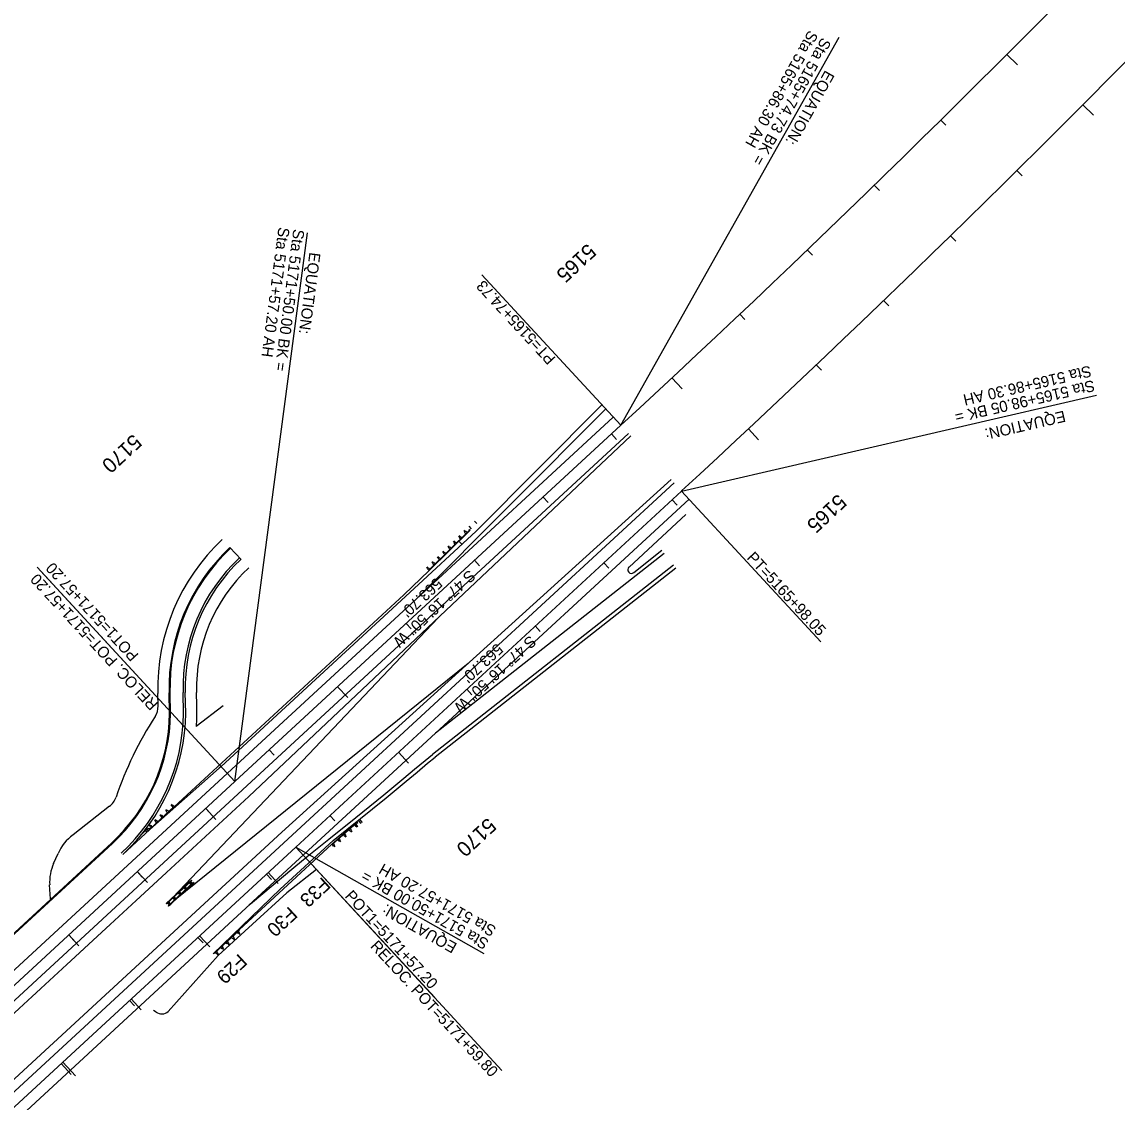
# Model space of a CAD drawing. Extents: x 2160877 to 2175861, y 601747 to 617724.
# Drawn here: x 2171979 to 2173154, y 613431 to 614591 of the extents above; entities that cross this region are included whole.
import ezdxf

# ---------------------------------------------------------------- set-up
doc = ezdxf.new("R2010")
doc.units = 0
for name, color, linetype in [('RD_HC_Cl', 7, 'Continuous'), ('RD_HC_CL_Rel', 7, 'Continuous'), ('RD_HC_Data', 7, 'Continuous'), ('RD_HC_Data_Rel', 7, 'Continuous'), ('RD_HC_Data_Tic', 7, 'Continuous'), ('RD_HC_Data_Tic_Rel', 7, 'Continuous'), ('RD_HC_TX_StaOther', 7, 'Continuous'), ('RD_PD_CstnLmt', 7, 'Continuous'), ('RD_PD_CstnLmt_TX', 7, 'Continuous'), ('RD_PD_Final_LnLine', 7, 'Continuous'), ('RD_PD_Final_TrvlWay', 7, 'Continuous'), ('RD_PD_GR', 7, 'Continuous'), ('RD_PD_MedBWall', 7, 'Continuous')]:
    doc.layers.add(name, color=color, linetype=linetype)

msp = doc.modelspace()

# ---------------------------------------------------------------- linework, layer by layer
at = {"layer": 'RD_HC_Cl'}
for p, q in [((2172621.5, 614157.6), (2172207.3, 613775.1)), ((2172686.6, 614087), (2172272.5, 613704.6)), ((2172207.3, 613775.1), (2163672.2, 605893.8)), ((2172272.5, 613704.6), (2163737.4, 605823.3))]:
    msp.add_line(p, q, dxfattribs=at)
for radius, end in [(14276, 327.03525), (14372, 326.23563)]:
    msp.add_arc((2162936.5, 624645.9), radius, 312.71947, end, dxfattribs=at)
at = {"layer": 'RD_HC_CL_Rel'}
for p, q in [((2172207.3, 613775.1), (2171340.7, 612974.9)), ((2172272.5, 613704.6), (2170771.4, 612318.6))]:
    msp.add_line(p, q, dxfattribs=at)
at = {"layer": 'RD_HC_Data'}
for p, q in [((2172621.5, 614157.6), (2172855.6, 614574.5)), ((2172207.3, 613775.1), (2172285.1, 614364.1)), ((2172621.5, 614157.6), (2172472.2, 614319.2)), ((2172686.6, 614087), (2173132, 614189.8)), ((2172686.6, 614087), (2172836, 613925.2)), ((2172207.3, 613775.1), (2171994.9, 614005.2)), ((2172272.5, 613704.6), (2172474.3, 613590.3)), ((2172272.5, 613704.6), (2172421.7, 613543))]:
    msp.add_line(p, q, dxfattribs=at)
at = {"layer": 'RD_HC_Data_Rel'}
for p, q in [((2172207.3, 613775.1), (2171998.5, 614001.3)), ((2172272.5, 613704.6), (2172493.8, 613464.9))]:
    msp.add_line(p, q, dxfattribs=at)
at = {"layer": 'RD_HC_Data_Tic'}
for p, q in [((2173035.7, 614555.9), (2173047.1, 614544.5)), ((2173117.4, 614501.8), (2173128.7, 614490.5)), ((2172964.8, 614485.4), (2172970.4, 614479.7)), ((2173046.6, 614431.2), (2173052.2, 614425.5)), ((2172893.4, 614415.4), (2172899, 614409.6)), ((2172975.3, 614361.1), (2172980.8, 614355.4)), ((2172821.5, 614345.9), (2172827, 614340.1)), ((2172903.5, 614291.5), (2172909, 614285.7)), ((2172749.1, 614276.9), (2172754.6, 614271.1)), ((2172831.2, 614222.4), (2172836.7, 614216.6)), ((2172676.2, 614208.4), (2172687.2, 614196.7)), ((2172611.4, 614148.3), (2172616.8, 614142.4)), ((2172758.4, 614153.8), (2172769.3, 614142.1)), ((2172537.9, 614080.4), (2172543.4, 614074.5)), ((2172676.5, 614077.7), (2172682, 614071.9)), ((2172464.5, 614012.6), (2172469.9, 614006.7)), ((2172603.1, 614009.9), (2172608.5, 614004)), ((2172391, 613944.7), (2172396.4, 613938.9)), ((2172529.6, 613942.1), (2172535, 613936.2)), ((2172317.5, 613876.9), (2172328.4, 613865.1)), ((2172456.1, 613874.2), (2172461.5, 613868.3)), ((2172244.1, 613809.1), (2172249.5, 613803.2)), ((2172382.7, 613806.4), (2172393.5, 613794.6)), ((2172175.9, 613746.1), (2172181.3, 613740.2)), ((2172309.2, 613738.5), (2172314.6, 613732.7)), ((2172102.4, 613678.3), (2172107.8, 613672.4)), ((2172241, 613675.6), (2172246.4, 613669.7)), ((2172028.9, 613610.4), (2172034.4, 613604.5)), ((2172167.5, 613607.7), (2172173, 613601.9)), ((2172094.1, 613539.9), (2172099.5, 613534)), ((2172020.6, 613472.1), (2172031.5, 613460.3))]:
    msp.add_line(p, q, dxfattribs=at)
at = {"layer": 'RD_HC_Data_Tic_Rel'}
for p, q in [((2172175.9, 613746.1), (2172186.7, 613734.4)), ((2172102.4, 613678.3), (2172113.3, 613666.5)), ((2172242.9, 613677.3), (2172253.8, 613665.6)), ((2172028.9, 613610.4), (2172039.8, 613598.7)), ((2172169.4, 613609.5), (2172180.3, 613597.7)), ((2172096, 613541.7), (2172106.8, 613529.9)), ((2172022.5, 613473.8), (2172036.1, 613459.1))]:
    msp.add_line(p, q, dxfattribs=at)
at = {"layer": 'RD_PD_CstnLmt'}
for p, q in [((2172124.8, 613856.2), (2172124.5, 613869.7)), ((2172166.4, 613856.6), (2172166.1, 613870.7)), ((2172194.7, 613856.3), (2172165.8, 613834)), ((2172072.6, 613748.5), (2172033.5, 613717.8)), ((2172012.7, 613687), (2172017.4, 613697.8)), ((2172294.8, 613680.4), (2172263.1, 613655.5)), ((2172009.3, 613648.9), (2172008.4, 613664.1)), ((2172263.1, 613655.5), (2172189.1, 613588.3)), ((2172135.6, 613528.1), (2172189.1, 613588.3)), ((2172120, 613529.7), (2172122.6, 613527.6))]:
    msp.add_line(p, q, dxfattribs=at)
for centre, radius, start, end in [((2172343.7, 613875.1), 219.3, 133.1773, 181.4209), ((2172343.7, 613875.1), 177.7, 133.1773, 181.4209), ((2172104.8, 613855.7), 20, 327.0543, 1.4209), ((2171944.2, 613851.1), 222.3, 355.5815, 1.4209), ((2172447.7, 613633.5), 388.6, 147.0543, 161.2766), ((2172060.7, 613764.6), 20, 306.2944, 341.2766), ((2172063.1, 613677.5), 50, 126.2944, 156.1048), ((2172058.4, 613666.8), 50, 156.1048, 183.118), ((2172128.8, 613535.4), 10, 231.8554, 312.7195)]:
    msp.add_arc(centre, radius, start, end, dxfattribs=at)
at = {"layer": 'RD_PD_Final_LnLine'}
for p, q in [((2172605.3, 614175.1), (2172401.6, 613970.8)), ((2172613.3, 614166.4), (2172401.6, 613970.8)), ((2172629.6, 614148.7), (2172215.5, 613766.3)), ((2172678.5, 614095.8), (2172264.3, 613713.4)), ((2172694.7, 614078.2), (2172422.5, 613826.8)), ((2172668, 614019.9), (2172422.5, 613826.8)), ((2172677.9, 614007.4), (2172419.4, 613804.1)), ((2172401.6, 613970.8), (2172199.2, 613784)), ((2172425.3, 613950.8), (2172140.7, 613650.6)), ((2172457.4, 613901.8), (2172143, 613648.1)), ((2172422.5, 613826.8), (2172222.3, 613642.1)), ((2172199.2, 613784), (2171332.6, 612983.8)), ((2172215.5, 613766.3), (2171348.9, 612966.1)), ((2172115.9, 613723.4), (2172086.9, 613696.6)), ((2172114.3, 613725.1), (2172108.2, 613719.4)), ((2172114.3, 613725.1), (2172115.9, 613723.4)), ((2172264.3, 613713.4), (2170763.3, 612327.4)), ((2172224.1, 613643.7), (2170779.6, 612309.8))]:
    msp.add_line(p, q, dxfattribs=at)
msp.add_lwpolyline([(2172224.1, 613643.7), (2172270.5, 613682.8), (2172284.9, 613694.4), (2172308.1, 613713.2), (2172336.9, 613736.4), (2172366.9, 613760.6), (2172388.6, 613778.6), (2172400.1, 613788.2), (2172411.3, 613797.7), (2172419.4, 613804.1)], dxfattribs=at)
at = {"layer": 'RD_PD_Final_TrvlWay'}
for p, q in [((2172601.2, 614179.5), (2172466, 614044)), ((2172632, 614146.1), (2172222.2, 613759)), ((2172675.3, 614099.3), (2172257.5, 613720.8)), ((2172691.2, 614061.8), (2172630.2, 614005.4)), ((2172466, 614044), (2172394.8, 613978.2)), ((2172665.6, 614023.1), (2172635.4, 613999.3)), ((2172680.4, 614004.2), (2172422.2, 613801.1)), ((2172394.8, 613978.2), (2172192.4, 613791.3)), ((2172192.4, 613791.3), (2172190.4, 613789.4)), ((2172190.4, 613789.4), (2172115.9, 613723.4)), ((2172222.2, 613759), (2171355.7, 612958.8)), ((2172257.5, 613720.8), (2170756.5, 612334.7)), ((2172312.6, 613711.7), (2172255.9, 613659.4)), ((2172255.9, 613659.4), (2172183.8, 613590.1))]:
    msp.add_line(p, q, dxfattribs=at)
msp.add_lwpolyline([(2172312.6, 613711.7), (2172369.4, 613757.5), (2172391.1, 613775.5), (2172402.7, 613785.2), (2172413.8, 613794.6), (2172422.2, 613801.1)], dxfattribs=at)
msp.add_arc((2172632.9, 614002.5), 4, 132.7195, 308.1849, dxfattribs=at)
at = {"layer": 'RD_PD_GR'}
for p, q in [((2172461.2, 614046.4), (2172458.6, 614049.1)), ((2172466.9, 614052), (2172464.3, 614054.7)), ((2172458.8, 614044.7), (2172415.3, 614001.9)), ((2172415.6, 614001.5), (2172459.8, 614045)), ((2172448.5, 614039.1), (2172447.2, 614037.9)), ((2172448.7, 614037.6), (2172447.8, 614038.5)), ((2172448.1, 614037), (2172449.3, 614038.2)), ((2172449.5, 614035.5), (2172448.1, 614037)), ((2172449.3, 614038.2), (2172450.7, 614036.8)), ((2172450.7, 614036.8), (2172449.5, 614035.5)), ((2172454.2, 614044.7), (2172452.9, 614043.5)), ((2172454.4, 614043.2), (2172453.5, 614044.1)), ((2172453.8, 614042.6), (2172455, 614043.8)), ((2172455.2, 614041.2), (2172453.8, 614042.6)), ((2172455, 614043.8), (2172456.4, 614042.4)), ((2172456.4, 614042.4), (2172455.2, 614041.2)), ((2172459.1, 614045.7), (2172458.4, 614045)), ((2172458.4, 614045), (2172458.8, 614044.7)), ((2172459.8, 614045), (2172459.1, 614045.7)), ((2172437.1, 614027.9), (2172435.8, 614026.6)), ((2172437.3, 614026.4), (2172436.4, 614027.2)), ((2172436.7, 614025.7), (2172437.9, 614027)), ((2172438.1, 614024.3), (2172436.7, 614025.7)), ((2172437.9, 614027), (2172439.3, 614025.5)), ((2172439.3, 614025.5), (2172438.1, 614024.3)), ((2172442.8, 614033.5), (2172441.5, 614032.2)), ((2172443, 614032), (2172442.1, 614032.9)), ((2172442.4, 614031.4), (2172443.6, 614032.6)), ((2172443.8, 614029.9), (2172442.4, 614031.4)), ((2172443.6, 614032.6), (2172445, 614031.2)), ((2172445, 614031.2), (2172443.8, 614029.9)), ((2172450.3, 614030.4), (2172447.7, 614033.1)), ((2172425.7, 614016.6), (2172424.4, 614015.4)), ((2172425.9, 614015.1), (2172425, 614016)), ((2172425.3, 614014.5), (2172426.5, 614015.7)), ((2172426.7, 614013.1), (2172425.3, 614014.5)), ((2172426.5, 614015.7), (2172427.9, 614014.3)), ((2172427.9, 614014.3), (2172426.7, 614013.1)), ((2172431.4, 614022.2), (2172430.1, 614021)), ((2172431.6, 614020.7), (2172430.7, 614021.6)), ((2172431, 614020.1), (2172432.2, 614021.4)), ((2172432.4, 614018.7), (2172431, 614020.1)), ((2172432.2, 614021.4), (2172433.6, 614019.9)), ((2172433.6, 614019.9), (2172432.4, 614018.7)), ((2172388.6, 613975.5), (2172415.6, 614001.5)), ((2172414.3, 614005.4), (2172413, 614004.2)), ((2172414.5, 614003.9), (2172413.6, 614004.8)), ((2172413.9, 614003.3), (2172415.1, 614004.5)), ((2172415.3, 614001.9), (2172413.9, 614003.3)), ((2172415.1, 614004.5), (2172416.5, 614003.1)), ((2172416.5, 614003.1), (2172415.3, 614001.9)), ((2172415.3, 614001.9), (2172415.6, 614001.5)), ((2172420, 614011), (2172418.7, 614009.8)), ((2172420.2, 614009.5), (2172419.3, 614010.4)), ((2172419.6, 614008.9), (2172420.8, 614010.1)), ((2172421, 614007.5), (2172419.6, 614008.9)), ((2172420.8, 614010.1), (2172422.2, 614008.7)), ((2172422.2, 614008.7), (2172421, 614007.5)), ((2172142.2, 613748), (2172388.6, 613975.5)), ((2172142.4, 613747.8), (2172115.9, 613723.4)), ((2172116.3, 613724.4), (2172142, 613748.2)), ((2172132.7, 613744), (2172133.9, 613745.1)), ((2172134.2, 613743.6), (2172133.3, 613744.6)), ((2172134.8, 613744.2), (2172133.5, 613743)), ((2172133.5, 613743), (2172134.9, 613741.6)), ((2172136.2, 613742.8), (2172134.8, 613744.2)), ((2172134.9, 613741.6), (2172136.2, 613742.8)), ((2172138.5, 613749.4), (2172139.8, 613750.6)), ((2172140, 613749.1), (2172139.2, 613750)), ((2172140.7, 613749.7), (2172139.4, 613748.5)), ((2172139.4, 613748.5), (2172140.7, 613747)), ((2172142, 613748.2), (2172140.7, 613749.7)), ((2172140.7, 613747), (2172142, 613748.2)), ((2172142, 613748.2), (2172142.4, 613747.8)), ((2172120.9, 613733.1), (2172122.2, 613734.3)), ((2172122.4, 613732.8), (2172121.6, 613733.7)), ((2172123, 613733.4), (2172121.8, 613732.2)), ((2172121.8, 613732.2), (2172123.1, 613730.7)), ((2172124.4, 613731.9), (2172123, 613733.4)), ((2172123.1, 613730.7), (2172124.4, 613731.9)), ((2172126.8, 613738.5), (2172128.1, 613739.7)), ((2172128.3, 613738.2), (2172127.4, 613739.1)), ((2172128.9, 613738.8), (2172127.6, 613737.6)), ((2172127.6, 613737.6), (2172129, 613736.1)), ((2172130.3, 613737.3), (2172128.9, 613738.8)), ((2172129, 613736.1), (2172130.3, 613737.3)), ((2172311.2, 613707.7), (2172338.3, 613731.4)), ((2172338.3, 613731.4), (2172339, 613730.7)), ((2172339.8, 613732.7), (2172342.3, 613729.9)), ((2172341.3, 613734), (2172343.8, 613731.2)), ((2172113, 613720.7), (2172110.4, 613723.4)), ((2172114.5, 613722), (2172111.9, 613724.8)), ((2172115, 613727.7), (2172116.3, 613728.9)), ((2172115.2, 613724.1), (2172116, 613724.8)), ((2172115.9, 613723.4), (2172115.2, 613724.1)), ((2172116.5, 613727.4), (2172115.7, 613728.3)), ((2172117.2, 613727.9), (2172115.9, 613726.8)), ((2172115.9, 613726.8), (2172117.2, 613725.3)), ((2172116, 613724.8), (2172116.3, 613724.4)), ((2172118.5, 613726.5), (2172117.2, 613727.9)), ((2172117.2, 613725.3), (2172118.5, 613726.5)), ((2172337.9, 613730.4), (2172311.5, 613707.3)), ((2172324.9, 613719), (2172323.6, 613717.9)), ((2172326.2, 613717.5), (2172324.9, 613719)), ((2172330.9, 613724.3), (2172329.6, 613723.1)), ((2172329.6, 613723.1), (2172330.9, 613721.6)), ((2172332.2, 613722.8), (2172330.9, 613724.3)), ((2172330.9, 613721.6), (2172332.2, 613722.8)), ((2172331.6, 613722.2), (2172332.4, 613721.3)), ((2172333.1, 613721.8), (2172331.7, 613720.7)), ((2172337, 613729.5), (2172335.6, 613728.4)), ((2172335.6, 613728.4), (2172336.9, 613726.9)), ((2172336.9, 613726.9), (2172338.3, 613728)), ((2172338.3, 613728), (2172337, 613729.5)), ((2172337.6, 613727.5), (2172338.4, 613726.5)), ((2172339.1, 613727.1), (2172337.8, 613725.9)), ((2172338.2, 613730), (2172337.9, 613730.4)), ((2172339, 613730.7), (2172338.2, 613730)), ((2172211.7, 613615.9), (2172311.2, 613707.7)), ((2172311.5, 613707.3), (2172311.2, 613707.7)), ((2172312.8, 613708.5), (2172311.5, 613707.3)), ((2172311.5, 613707.3), (2172312.8, 613705.8)), ((2172314.2, 613707), (2172312.8, 613708.5)), ((2172318.9, 613713.8), (2172317.6, 613712.6)), ((2172317.6, 613712.6), (2172318.9, 613711.1)), ((2172320.2, 613712.3), (2172318.9, 613713.8)), ((2172318.9, 613711.1), (2172320.2, 613712.3)), ((2172319.5, 613711.7), (2172320.4, 613710.7)), ((2172321, 613711.3), (2172319.7, 613710.2)), ((2172323.6, 613717.9), (2172324.9, 613716.4)), ((2172324.9, 613716.4), (2172326.2, 613717.5)), ((2172325.6, 613716.9), (2172326.4, 613716)), ((2172327, 613716.6), (2172325.7, 613715.4)), ((2172312.8, 613705.8), (2172314.2, 613707)), ((2172313.5, 613706.4), (2172314.3, 613705.5)), ((2172315, 613706.1), (2172313.7, 613704.9)), ((2172160.6, 613669.1), (2172133.4, 613644)), ((2172133.7, 613643.7), (2172160.9, 613668.8)), ((2172135.5, 613641.7), (2172162.7, 613666.8)), ((2172163.1, 613666.4), (2172135.9, 613641.3)), ((2172152, 613661.4), (2172153.3, 613662.6)), ((2172152.4, 613660.9), (2172153.7, 613662.1)), ((2172153.8, 613659.5), (2172152.4, 613660.9)), ((2172153.5, 613661), (2172152.7, 613662)), ((2172154.2, 613661.6), (2172152.9, 613660.5)), ((2172152.9, 613660.5), (2172154.3, 613659)), ((2172153.7, 613662.1), (2172155.1, 613660.7)), ((2172155.1, 613660.7), (2172153.8, 613659.5)), ((2172155.5, 613660.2), (2172154.2, 613661.6)), ((2172157.9, 613666.8), (2172159.2, 613668)), ((2172158.3, 613666.4), (2172159.6, 613667.6)), ((2172159.7, 613664.9), (2172158.3, 613666.4)), ((2172159.4, 613666.5), (2172158.6, 613667.4)), ((2172160.1, 613667.1), (2172158.8, 613665.9)), ((2172158.8, 613665.9), (2172160.1, 613664.4)), ((2172159.6, 613667.6), (2172161, 613666.1)), ((2172161, 613666.1), (2172159.7, 613664.9)), ((2172161.4, 613665.6), (2172160.1, 613667.1)), ((2172160.1, 613664.4), (2172161.4, 613665.6)), ((2172160.3, 613665.5), (2172161.2, 613664.6)), ((2172160.5, 613664), (2172161.8, 613665.2)), ((2172160.9, 613668.8), (2172160.6, 613669.1)), ((2172162.7, 613666.8), (2172163.1, 613666.4)), ((2172140.3, 613650.5), (2172141.6, 613651.7)), ((2172140.7, 613650.1), (2172142, 613651.3)), ((2172142, 613648.6), (2172140.7, 613650.1)), ((2172141.8, 613650.2), (2172140.9, 613651.1)), ((2172142.4, 613650.8), (2172141.1, 613649.6)), ((2172141.1, 613649.6), (2172142.5, 613648.1)), ((2172142, 613651.3), (2172143.3, 613649.8)), ((2172143.3, 613649.8), (2172142, 613648.6)), ((2172143.8, 613649.3), (2172142.4, 613650.8)), ((2172142.5, 613648.1), (2172143.8, 613649.3)), ((2172142.7, 613649.2), (2172143.5, 613648.3)), ((2172142.9, 613647.7), (2172144.2, 613648.9)), ((2172146.2, 613655.9), (2172147.5, 613657.1)), ((2172146.6, 613655.5), (2172147.9, 613656.7)), ((2172147.9, 613654), (2172146.6, 613655.5)), ((2172147.7, 613655.6), (2172146.8, 613656.5)), ((2172148.3, 613656.2), (2172147, 613655)), ((2172147, 613655), (2172148.4, 613653.6)), ((2172147.9, 613656.7), (2172149.2, 613655.2)), ((2172149.2, 613655.2), (2172147.9, 613654)), ((2172149.7, 613654.7), (2172148.3, 613656.2)), ((2172148.4, 613653.6), (2172149.7, 613654.7)), ((2172148.6, 613654.6), (2172149.4, 613653.7)), ((2172148.8, 613653.1), (2172150.1, 613654.3)), ((2172154.3, 613659), (2172155.5, 613660.2)), ((2172154.4, 613660.1), (2172155.3, 613659.2)), ((2172154.6, 613658.6), (2172155.9, 613659.7)), ((2172133.4, 613644), (2172133.7, 613643.7)), ((2172134.4, 613645.1), (2172135.7, 613646.3)), ((2172134.8, 613644.7), (2172136.1, 613645.9)), ((2172136.2, 613643.2), (2172134.8, 613644.7)), ((2172135.9, 613644.8), (2172135.1, 613645.7)), ((2172136.5, 613645.4), (2172135.3, 613644.2)), ((2172135.3, 613644.2), (2172136.6, 613642.7)), ((2172135.9, 613641.3), (2172135.5, 613641.7)), ((2172136.1, 613645.9), (2172137.5, 613644.4)), ((2172137.5, 613644.4), (2172136.2, 613643.2)), ((2172137.9, 613643.9), (2172136.5, 613645.4)), ((2172136.6, 613642.7), (2172137.9, 613643.9)), ((2172136.8, 613643.8), (2172137.7, 613642.9)), ((2172137, 613642.3), (2172138.3, 613643.5)), ((2172138.4, 613648), (2172138.1, 613648.3)), ((2172140.2, 613646), (2172140.5, 613645.6)), ((2172211.8, 613615.9), (2172184.6, 613590.8)), ((2172184.9, 613590.4), (2172212.1, 613615.5)), ((2172209.5, 613613.1), (2172210.8, 613614.3)), ((2172210.8, 613614.3), (2172212.2, 613612.9)), ((2172212.1, 613615.5), (2172211.8, 613615.9)), ((2172197.8, 613602.3), (2172199, 613603.5)), ((2172199.1, 613600.8), (2172197.8, 613602.3)), ((2172199, 613603.5), (2172200.4, 613602)), ((2172200.4, 613602), (2172199.1, 613600.8)), ((2172203.6, 613607.7), (2172204.9, 613608.9)), ((2172205, 613606.3), (2172203.6, 613607.7)), ((2172204.9, 613608.9), (2172206.3, 613607.4)), ((2172206.3, 613607.4), (2172205, 613606.3)), ((2172205.6, 613606.8), (2172206.5, 613605.9)), ((2172205.8, 613605.3), (2172207.1, 613606.5)), ((2172210.9, 613611.7), (2172209.5, 613613.1)), ((2172212.2, 613612.9), (2172210.9, 613611.7)), ((2172211.5, 613612.3), (2172212.4, 613611.4)), ((2172211.7, 613610.8), (2172213, 613611.9)), ((2172184.6, 613590.8), (2172184.9, 613590.4)), ((2172186, 613591.4), (2172187.3, 613592.6)), ((2172187.4, 613590), (2172186, 613591.4)), ((2172187.3, 613592.6), (2172188.6, 613591.2)), ((2172188.6, 613591.2), (2172187.4, 613590)), ((2172188, 613590.6), (2172188.9, 613589.6)), ((2172188.2, 613589.1), (2172189.5, 613590.2)), ((2172189.6, 613594.7), (2172189.2, 613595.1)), ((2172191.9, 613596.9), (2172193.2, 613598.1)), ((2172193.2, 613595.4), (2172191.9, 613596.9)), ((2172193.2, 613598.1), (2172194.5, 613596.6)), ((2172194.5, 613596.6), (2172193.2, 613595.4)), ((2172193.9, 613596), (2172194.7, 613595.1)), ((2172194.1, 613594.5), (2172195.4, 613595.7)), ((2172199.8, 613601.4), (2172200.6, 613600.5)), ((2172200, 613599.9), (2172201.3, 613601.1))]:
    msp.add_line(p, q, dxfattribs=at)
at = {"layer": 'RD_PD_MedBWall'}
for p, q in [((2172201.9, 614026.3), (2172213.8, 614013.6)), ((2172137.2, 613848.1), (2172136.6, 613870.2)), ((2172138.2, 613848.1), (2172137.6, 613870.2)), ((2172152.2, 613848.2), (2172151.6, 613870.5)), ((2172154.5, 613848.4), (2172153.9, 613870.6)), ((2172075.1, 613709.3), (2171312.7, 613005.3)), ((2172075.8, 613708.6), (2171313.4, 613004.6))]:
    msp.add_line(p, q, dxfattribs=at)
for centre, radius, start, end in [((2172343.5, 613875.3), 207, 133.1773, 181.4209), ((2172343.5, 613875.3), 206, 133.1773, 181.4209), ((2172343.5, 613875.3), 192, 133.1773, 181.4209), ((2172343.5, 613875.3), 189.7, 133.1773, 181.4209), ((2171944.2, 613851.1), 210.3, 312.7195, 359.2641), ((2171944.2, 613851.1), 193, 312.7195, 359.12), ((2171944.2, 613851.1), 194, 312.7195, 359.1259), ((2171944.2, 613851.1), 208, 312.7195, 359.2045)]:
    msp.add_arc(centre, radius, start, end, dxfattribs=at)

# ---------------------------------------------------------------- texts
at = {"layer": 'RD_HC_Data'}
for s, rotation, p in [('Sta 5165+86.30 AH', 240.6833, (2172823.3, 614582.6)), ('Sta 5165+74.73 BK = ', 240.6833, (2172837.3, 614574.8)), ('EQUATION:', 240.6833, (2172840.9, 614539.6)), ('Sta 5171+57.20 AH', 262.4748, (2172254.1, 614370.8)), ('Sta 5171+50.00 BK = ', 262.4748, (2172270, 614368.7)), ('EQUATION:', 262.4748, (2172287.3, 614343.8)), ('PT=5165+74.73', 132.7195, (2172552.2, 614229.7)), ('Sta 5165+86.30 AH', 192.9905, (2173124.9, 614221.9)), ('Sta 5165+98.05 BK = ', 192.9905, (2173128.5, 614206.3)), ('EQUATION:', 192.9905, (2173097.1, 614173.4)), ('PT=5165+98.05', 312.7195, (2172755.9, 614014.9)), ('POT1=5171+57.20', 132.7195, (2172104.7, 613911.1)), ('Sta 5171+57.20 AH', 150.4677, (2172488.7, 613618.3)), ('Sta 5171+50.00 BK = ', 150.4677, (2172480.8, 613604.4)), ('POT1=5171+57.20', 312.7195, (2172324.6, 613651.5)), ('EQUATION:', 150.4677, (2172446.6, 613600.5))]:
    msp.add_text(s, height=12, rotation=rotation, dxfattribs=at).set_placement(p)
at = {"layer": 'RD_HC_Data_Rel'}
for s, rotation, p in [('RELOC. POT=5171+57.20', 132.7195, (2172125.6, 613858.5)), ('RELOC. POT=5171+59.80', 312.7195, (2172351.8, 613597.6))]:
    msp.add_text(s, height=12, rotation=rotation, dxfattribs=at).set_placement(p)
at = {"layer": 'RD_HC_TX_StaOther'}
for s, height, rotation, p in [('5165', 16, 223.0194, (2172585.6, 614353.6)), ('5170', 16, 222.7195, (2172098, 614149)), ('5165', 16, 223.1104, (2172854.4, 614084.7)), ('S 47%%d 16\' 50" W', 12, 222.7195, (2172458.6, 614003.1)), ("563.70'", 12, 222.7195, (2172423, 613994.7)), ('S 47%%d 16\' 50" W', 12, 222.7195, (2172523.8, 613932.6)), ("563.70'", 12, 222.7195, (2172488.2, 613924.2)), ('5170', 16, 222.7195, (2172478.5, 613737))]:
    msp.add_text(s, height=height, rotation=rotation, dxfattribs=at).set_placement(p)
at = {"layer": 'RD_PD_CstnLmt_TX'}
for s, p in [('F33', (2172301.1, 613673.3)), ('F30', (2172265.6, 613641.6)), ('F29', (2172211.6, 613590.9))]:
    msp.add_text(s, height=15, rotation=222.7195, dxfattribs=at).set_placement(p)

doc.saveas('drawing.dxf')
